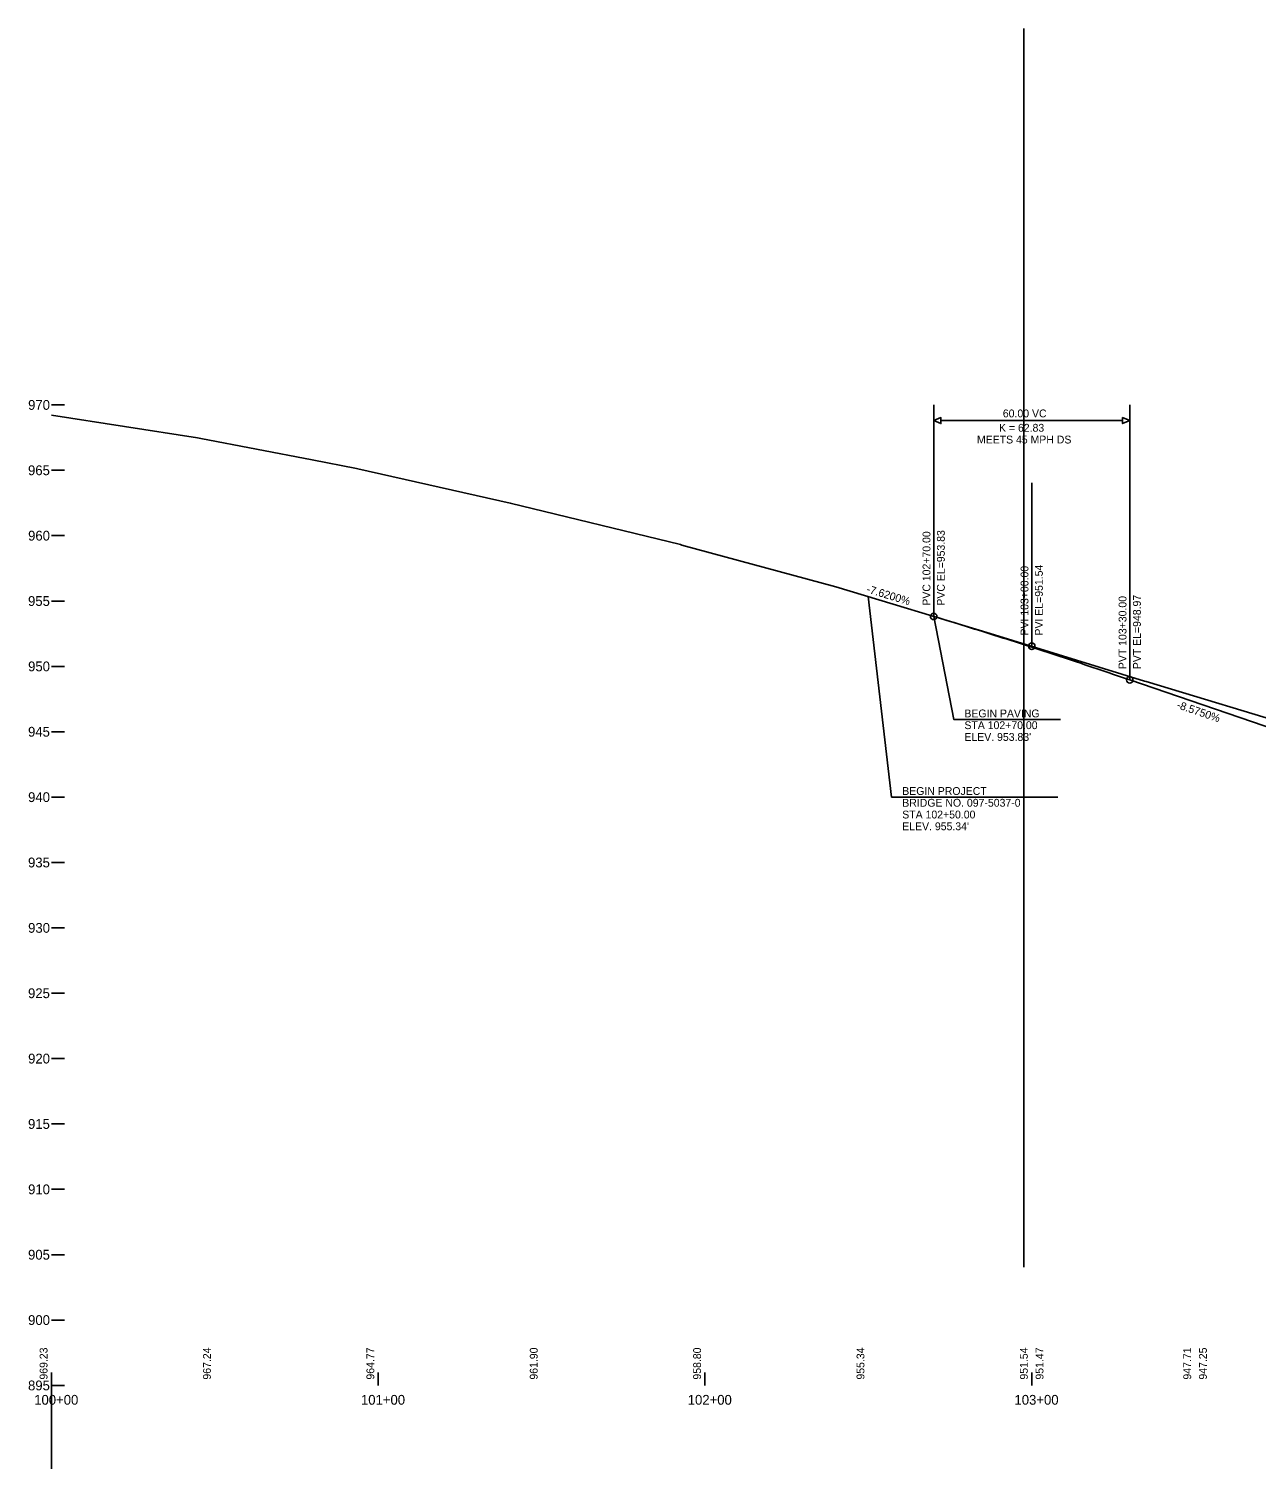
# Model space of a CAD drawing. Extents: x 2091593 to 2093109, y 1330214 to 1331965.
# Drawn here: x 2091592.7 to 2091968.5, y 1331527.6 to 1331965.3 of the extents above; entities that cross this region are included whole.
import ezdxf

# ---------------------------------------------------------------- set-up
doc = ezdxf.new("R2010")
doc.units = 0
for name, color, linetype in [('ATMS_P_ITS-Device-and-Conduit', 7, 'Continuous'), ('Default', 7, 'Continuous'), ('PROF_E_Ground-Line', 7, 'Continuous'), ('PROF_E_Ground-Text', 7, 'Continuous'), ('PROF_P_CONSTCL-Cell', 7, 'Continuous'), ('PROF_P_CONSTCL-Line', 7, 'Continuous'), ('PROF_P_Finish-Elev-Text', 7, 'Continuous'), ('PROF_P_Finish-Text', 7, 'Continuous'), ('SHT_B_Grid-Elevation-Text', 7, 'Continuous'), ('SHT_B_Grid-Station-Text', 7, 'Continuous'), ('SHT_B_Major-Offset-Tic-Line', 7, 'Continuous'), ('SHT_B_Major-Station-Tic-Line', 7, 'Continuous')]:
    doc.layers.add(name, color=color, linetype=linetype)

msp = doc.modelspace()

# ---------------------------------------------------------------- linework, layer by layer
at = {"layer": 'ATMS_P_ITS-Device-and-Conduit'}
for p, q in [((2091897.29, 1331586.36), (2091897.29, 1331965.35)), ((2091599.69, 1331550.21), (2091599.69, 1330214.3))]:
    msp.add_line(p, q, dxfattribs=at)
at = {"layer": 'PROF_E_Ground-Line'}
msp.add_lwpolyline([(2091599.69, 1331847.11), (2091644.41, 1331840.12), (2091645.4, 1331839.98), (2091679.53, 1331833.39), (2091693.03, 1331830.79), (2091693.47, 1331830.69), (2091740.1, 1331820.16), (2091740.1, 1331820.16), (2091792.16, 1331807.46), (2091792.59, 1331807.34), (2091839.77, 1331794.58), (2091887, 1331780.27), (2091887.03, 1331780.26), (2091934.17, 1331765.72), (2091934.7, 1331765.56), (2091982.53, 1331751.11)], dxfattribs=at)
at = {"layer": 'PROF_P_CONSTCL-Cell'}
for centre in [(2091869.69, 1331785.51), (2091899.69, 1331776.37), (2091929.69, 1331766.08)]:
    msp.add_circle(centre, 1, dxfattribs=at)
at = {"layer": 'PROF_P_CONSTCL-Line'}
msp.add_line((2091929.69, 1331766.08), (2091979.69, 1331748.93), dxfattribs=at)
msp.add_lwpolyline([(2091869.69, 1331785.51), (2091870.94, 1331785.13), (2091872.19, 1331784.75), (2091873.44, 1331784.36), (2091874.69, 1331783.98), (2091875.94, 1331783.59), (2091877.19, 1331783.21), (2091878.44, 1331782.82), (2091879.69, 1331782.43), (2091880.94, 1331782.04), (2091882.19, 1331781.65), (2091883.44, 1331781.26), (2091884.69, 1331780.87), (2091885.94, 1331780.47), (2091887.19, 1331780.08), (2091888.44, 1331779.68), (2091889.69, 1331779.29), (2091890.94, 1331778.89), (2091892.19, 1331778.49), (2091893.44, 1331778.09), (2091894.69, 1331777.69), (2091895.94, 1331777.29), (2091897.19, 1331776.89), (2091898.44, 1331776.48), (2091900.94, 1331775.67), (2091902.19, 1331775.27), (2091903.44, 1331774.86), (2091904.69, 1331774.45), (2091905.94, 1331774.04), (2091907.19, 1331773.63), (2091908.44, 1331773.22), (2091909.69, 1331772.81), (2091910.94, 1331772.39), (2091912.19, 1331771.98), (2091913.44, 1331771.56), (2091914.69, 1331771.15), (2091915.94, 1331770.73), (2091917.19, 1331770.31), (2091918.44, 1331769.89), (2091919.69, 1331769.47), (2091920.94, 1331769.05), (2091922.19, 1331768.63), (2091923.44, 1331768.21), (2091924.69, 1331767.78), (2091925.94, 1331767.36), (2091927.19, 1331766.93), (2091928.44, 1331766.5), (2091929.69, 1331766.08)], dxfattribs=at)
at = {"layer": 'PROF_P_Finish-Text'}
for p, q in [((2091869.69, 1331785.51), (2091869.69, 1331850.21)), ((2091929.69, 1331766.08), (2091929.69, 1331850.21)), ((2091869.69, 1331785.51), (2091869.69, 1331833.51)), ((2091899.69, 1331776.37), (2091899.69, 1331826.37)), ((2091929.69, 1331766.08), (2091929.69, 1331816.08))]:
    msp.add_line(p, q, dxfattribs=at)
for points in [[(2091869.69, 1331845.41), (2091871.91, 1331844.49), (2091871.91, 1331846.32)], [(2091929.69, 1331845.41), (2091927.48, 1331846.32), (2091927.48, 1331844.49)]]:
    msp.add_lwpolyline(points, close=True, dxfattribs=at)
for points in [[(2091871.91, 1331845.41), (2091927.48, 1331845.41)], [(2091907.7, 1331730.21), (2091856.81, 1331730.21), (2091849.69, 1331791.58)], [(2091908.55, 1331753.99), (2091875.82, 1331753.99), (2091869.69, 1331785.51)]]:
    msp.add_lwpolyline(points, dxfattribs=at)
at = {"layer": 'SHT_B_Major-Offset-Tic-Line'}
for p, q in [((2091599.69, 1331850.21), (2091603.69, 1331850.21)), ((2091599.69, 1331850.21), (2091603.69, 1331850.21)), ((2091599.69, 1331830.21), (2091603.69, 1331830.21)), ((2091599.69, 1331810.21), (2091603.69, 1331810.21)), ((2091599.69, 1331790.21), (2091603.69, 1331790.21)), ((2091599.69, 1331770.21), (2091603.69, 1331770.21)), ((2091599.69, 1331750.21), (2091603.69, 1331750.21)), ((2091599.69, 1331730.21), (2091603.69, 1331730.21)), ((2091599.69, 1331710.21), (2091603.69, 1331710.21)), ((2091599.69, 1331690.21), (2091603.69, 1331690.21)), ((2091599.69, 1331670.21), (2091603.69, 1331670.21)), ((2091599.69, 1331650.21), (2091603.69, 1331650.21)), ((2091599.69, 1331630.21), (2091603.69, 1331630.21)), ((2091599.69, 1331610.21), (2091603.69, 1331610.21)), ((2091599.69, 1331590.21), (2091603.69, 1331590.21)), ((2091599.69, 1331570.21), (2091603.69, 1331570.21)), ((2091599.69, 1331550.21), (2091603.69, 1331550.21))]:
    msp.add_line(p, q, dxfattribs=at)
at = {"layer": 'SHT_B_Major-Station-Tic-Line'}
for p, q in [((2091599.69, 1331550.21), (2091599.69, 1331554.21)), ((2091699.69, 1331550.21), (2091699.69, 1331554.21)), ((2091799.69, 1331550.21), (2091799.69, 1331554.21)), ((2091899.69, 1331550.21), (2091899.69, 1331554.21))]:
    msp.add_line(p, q, dxfattribs=at)

# ---------------------------------------------------------------- texts
at = {"layer": 'Default'}
msp.add_text('-', height=0.002, dxfattribs=at).set_placement((2091599.69, 1331550.21))
at = {"layer": 'PROF_E_Ground-Text'}
for s, p in [('  969.23', (2091598.49, 1331550.21)), ('  967.24', (2091648.49, 1331550.21)), ('  964.77', (2091698.49, 1331550.21)), ('  961.90', (2091748.49, 1331550.21)), ('  958.80', (2091798.49, 1331550.21)), ('  955.34', (2091848.49, 1331550.21)), ('  951.54', (2091898.49, 1331550.21)), ('  947.71', (2091948.49, 1331550.21))]:
    msp.add_text(s, height=2.4, rotation=90, dxfattribs=at).set_placement(p)
at = {"layer": 'PROF_P_Finish-Elev-Text'}
for s, p in [('  951.47', (2091903.29, 1331550.21)), ('  947.25', (2091953.29, 1331550.21))]:
    msp.add_text(s, height=2.4, rotation=90, dxfattribs=at).set_placement(p)
at = {"layer": 'PROF_P_Finish-Text'}
for s, p in [('60.00 VC', (2091890.86, 1331846.41)), ('MEETS 45 MPH DS', (2091882.94, 1331838.41)), ('K = 62.83', (2091889.69, 1331842.01))]:
    msp.add_text(s, height=2.4, dxfattribs=at).set_placement(p)
for s, height, rotation, p in [('  PVC 102+70.00', 2.4, 90, (2091868.69, 1331787.01)), ('  PVC EL=953.83', 2.4, 90, (2091873.09, 1331787.01)), ('  PVI 103+00.00', 2.4, 90, (2091898.69, 1331777.87)), ('  PVI EL=951.54', 2.4, 90, (2091903.09, 1331777.87)), ('-7.6200%', 2.4, 343.0488, (2091848.95, 1331792.88)), ('  PVT 103+30.00', 2.4, 90, (2091928.69, 1331767.58)), ('  PVT EL=948.97', 2.4, 90, (2091933.09, 1331767.58)), ('-8.5750%', 2.4, 341.068, (2091943.87, 1331757.51)), ('STA 102+70.00', 2.3994, 0.0064, (2091879.1, 1331751.02)), ('BEGIN PAVING', 2.3994, 0.0064, (2091879.1, 1331754.61)), ("ELEV. 953.83'", 2.3994, 0.0064, (2091879.1, 1331747.42)), ('BEGIN PROJECT', 2.3994, 0.0064, (2091860.08, 1331730.88)), ('BRIDGE NO. 097-5037-0', 2.3994, 0.0064, (2091860.08, 1331727.28)), ('STA 102+50.00', 2.3994, 0.0064, (2091860.08, 1331723.68)), ("ELEV. 955.34'", 2.3994, 0.0064, (2091860.08, 1331720.08))]:
    msp.add_text(s, height=height, rotation=rotation, dxfattribs=at).set_placement(p)
at = {"layer": 'SHT_B_Grid-Elevation-Text'}
for s, p in [('970', (2091592.55, 1331848.71)), ('970', (2091592.55, 1331848.71)), ('965', (2091592.53, 1331828.71)), ('960', (2091592.55, 1331808.71)), ('955', (2091592.53, 1331788.71)), ('950', (2091592.55, 1331768.71)), ('945', (2091592.53, 1331748.71)), ('940', (2091592.55, 1331728.71)), ('935', (2091592.53, 1331708.71)), ('930', (2091592.55, 1331688.71)), ('925', (2091592.53, 1331668.71)), ('920', (2091592.55, 1331648.71)), ('915', (2091592.53, 1331628.71)), ('910', (2091592.55, 1331608.71)), ('905', (2091592.53, 1331588.71)), ('900', (2091592.55, 1331568.71)), ('895', (2091592.53, 1331548.71))]:
    msp.add_text(s, height=3, dxfattribs=at).set_placement(p)
at = {"layer": 'SHT_B_Grid-Station-Text'}
for s, p in [('100+00', (2091594.42, 1331544.31)), ('101+00', (2091694.42, 1331544.31)), ('102+00', (2091794.42, 1331544.31)), ('103+00', (2091894.42, 1331544.31))]:
    msp.add_text(s, height=3, dxfattribs=at).set_placement(p)

doc.saveas('drawing.dxf')
